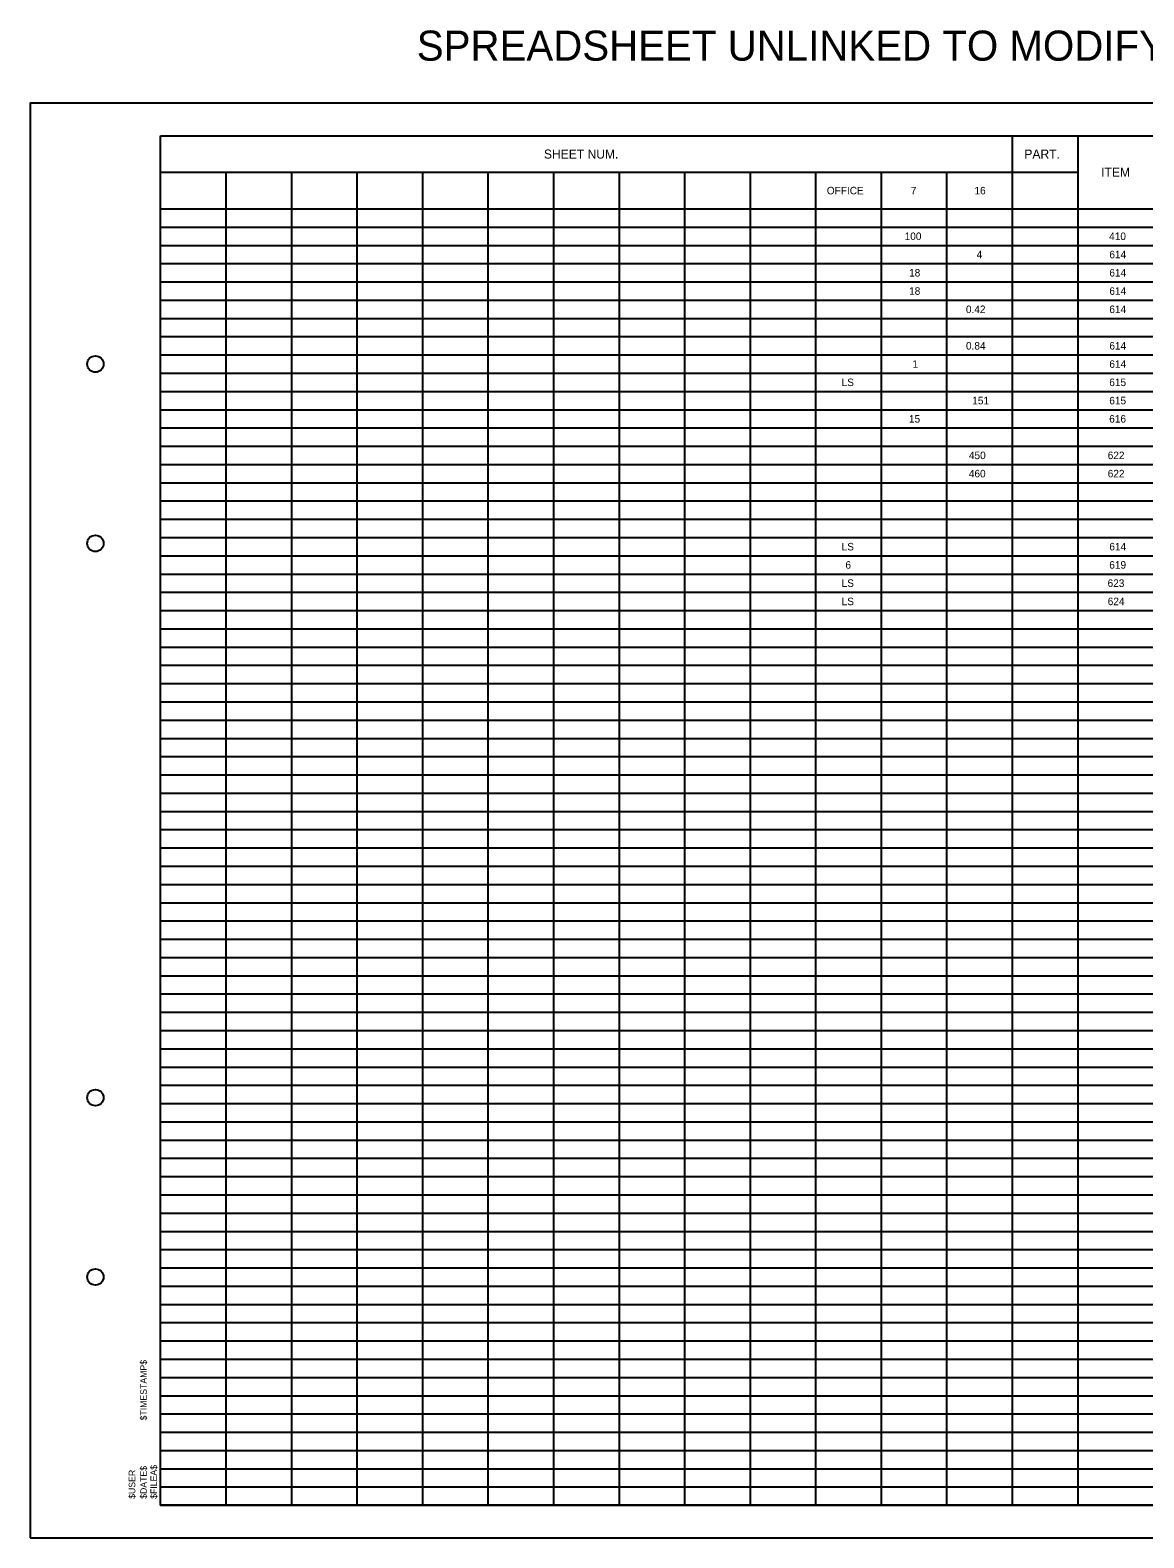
# Model space of a CAD drawing. Extents: x 0 to 34, y 0 to 23.1.
# Drawn here: x 0 to 17.07, y 0 to 23.12 of the extents above; entities that cross this region are included whole.
import ezdxf

# ---------------------------------------------------------------- set-up
doc = ezdxf.new("R2010")
doc.units = 0
for name, color, linetype in [('SH_Border', 7, 'Continuous'), ('SH_Cut_Line', 7, 'Continuous'), ('SH_Data', 7, 'Continuous'), ('SH_Text', 7, 'Continuous')]:
    doc.layers.add(name, color=color, linetype=linetype)

msp = doc.modelspace()

# ---------------------------------------------------------------- linework, layer by layer
at = {"layer": 'SH_Border'}
msp.add_lwpolyline([(2, 21.5), (33.5, 21.5), (33.5, 0.5), (2, 0.5)], close=True, dxfattribs=at)
for centre in [(1, 18), (1, 15.25), (1, 6.75), (1, 4)]:
    msp.add_circle(centre, 0.125, dxfattribs=at)
at = {"layer": 'SH_Cut_Line'}
msp.add_lwpolyline([(0, 0), (34, 0), (34, 22), (0, 22)], close=True, dxfattribs=at)
at = {"layer": 'SH_Text'}
for p, q in [((2, 21.5), (2, 21.5)), ((2, 21.5), (32.5, 21.5)), ((2, 0.5), (2, 21.5)), ((15.06, 0.5), (15.06, 21.5)), ((16.064, 0.5), (16.064, 21.5)), ((2, 20.94), (16.064, 20.94)), ((3.005, 0.5), (3.005, 20.94)), ((4.009, 0.5), (4.009, 20.94)), ((5.014, 0.5), (5.014, 20.94)), ((6.018, 0.5), (6.018, 20.94)), ((7.023, 0.5), (7.023, 20.94)), ((8.028, 0.5), (8.028, 20.94)), ((9.032, 0.5), (9.032, 20.94)), ((10.037, 0.5), (10.037, 20.94)), ((11.041, 0.5), (11.041, 20.94)), ((12.046, 0.5), (12.046, 20.94)), ((13.05, 0.5), (13.05, 20.94)), ((14.055, 0.5), (14.055, 20.94)), ((2, 20.38), (15.06, 20.38)), ((14.055, 20.38), (32.5, 20.38)), ((2, 20.1), (32.5, 20.1)), ((2, 19.82), (32.5, 19.82)), ((2, 19.54), (32.5, 19.54)), ((2, 19.26), (32.5, 19.26)), ((2, 18.98), (32.5, 18.98)), ((2, 18.7), (32.5, 18.7)), ((2, 18.42), (32.5, 18.42)), ((2, 18.14), (32.5, 18.14)), ((2, 17.86), (32.5, 17.86)), ((2, 17.58), (32.5, 17.58)), ((2, 17.3), (32.5, 17.3)), ((2, 17.02), (32.5, 17.02)), ((2, 16.74), (32.5, 16.74)), ((2, 16.46), (32.5, 16.46)), ((2, 16.18), (32.5, 16.18)), ((2, 15.9), (32.5, 15.9)), ((2, 15.62), (32.5, 15.62)), ((2, 15.34), (32.5, 15.34)), ((2, 15.06), (32.5, 15.06)), ((2, 14.78), (32.5, 14.78)), ((2, 14.5), (32.5, 14.5)), ((2, 14.22), (32.5, 14.22)), ((2, 13.94), (32.5, 13.94)), ((2, 13.66), (32.5, 13.66)), ((2, 13.38), (32.5, 13.38)), ((2, 13.1), (32.5, 13.1)), ((2, 12.82), (32.5, 12.82)), ((2, 12.54), (32.5, 12.54)), ((2, 12.26), (32.5, 12.26)), ((2, 11.98), (32.5, 11.98)), ((2, 11.7), (32.5, 11.7)), ((2, 11.42), (32.5, 11.42)), ((2, 11.14), (32.5, 11.14)), ((2, 10.86), (32.5, 10.86)), ((2, 10.58), (32.5, 10.58)), ((2, 10.3), (32.5, 10.3)), ((2, 10.02), (32.5, 10.02)), ((2, 9.74), (32.5, 9.74)), ((2, 9.46), (32.5, 9.46)), ((2, 9.18), (32.5, 9.18)), ((2, 8.9), (32.5, 8.9)), ((2, 8.62), (32.5, 8.62)), ((2, 8.34), (32.5, 8.34)), ((2, 8.06), (32.5, 8.06)), ((2, 7.78), (32.5, 7.78)), ((2, 7.5), (32.5, 7.5)), ((2, 7.22), (32.5, 7.22)), ((2, 6.94), (32.5, 6.94)), ((2, 6.66), (32.5, 6.66)), ((2, 6.38), (32.5, 6.38)), ((2, 6.1), (32.5, 6.1)), ((2, 5.82), (32.5, 5.82)), ((2, 5.54), (32.5, 5.54)), ((2, 5.26), (32.5, 5.26)), ((2, 4.98), (32.5, 4.98)), ((2, 4.7), (32.5, 4.7)), ((2, 4.42), (32.5, 4.42)), ((2, 4.14), (32.5, 4.14)), ((2, 3.86), (32.5, 3.86)), ((2, 3.58), (32.5, 3.58)), ((2, 3.3), (32.5, 3.3)), ((2, 3.02), (32.5, 3.02)), ((2, 2.74), (32.5, 2.74)), ((2, 2.46), (32.5, 2.46)), ((2, 2.18), (32.5, 2.18)), ((2, 1.9), (32.5, 1.9)), ((2, 1.62), (32.5, 1.62)), ((2, 1.34), (32.5, 1.34)), ((2, 1.06), (32.5, 1.06)), ((2, 0.78), (32.5, 0.78)), ((2, 0.5), (32.5, 0.5))]:
    msp.add_line(p, q, dxfattribs=at)

# ---------------------------------------------------------------- texts
at = {"layer": 'SH_Data'}
for s, p in [('$TIMESTAMP$', (1.788, 1.8)), ('$USER', (1.611, 0.598)), ('$DATE$', (1.788, 0.598)), ('$FILEA$', (1.944, 0.598))]:
    msp.add_text(s, height=0.1, rotation=89.9931, dxfattribs=at).set_placement(p)
at = {"layer": 'SH_Text'}
for s, height, p in [('SPREADSHEET UNLINKED TO MODIFY PORTABLE BARRIER ITEMS.', 0.46136, (5.927, 22.652)), ('SHEET NUM.', 0.1384, (7.876, 21.151)), ('PART.', 0.1384, (15.241, 21.151)), ('ITEM', 0.1384, (16.419, 20.871)), ('OFFICE', 0.1153, (12.213, 20.602)), ('7', 0.115, (13.5, 20.602)), ('16', 0.1153, (14.476, 20.602)), ('100', 0.1153, (13.406, 19.902)), ('410', 0.1153, (16.541, 19.902)), ('4', 0.115, (14.509, 19.622)), ('614', 0.1153, (16.544, 19.622)), ('18', 0.1153, (13.474, 19.342)), ('614', 0.1153, (16.544, 19.342)), ('18', 0.1153, (13.474, 19.062)), ('614', 0.1153, (16.544, 19.062)), ('0.42', 0.1153, (14.345, 18.782)), ('614', 0.1153, (16.544, 18.782)), ('0.84', 0.1153, (14.346, 18.222)), ('614', 0.1153, (16.544, 18.222)), ('1', 0.115, (13.525, 17.942)), ('614', 0.1153, (16.544, 17.942)), ('LS', 0.1153, (12.44, 17.662)), ('615', 0.1153, (16.543, 17.662)), ('151', 0.1153, (14.442, 17.382)), ('615', 0.1153, (16.543, 17.382)), ('15', 0.1153, (13.472, 17.102)), ('616', 0.1153, (16.542, 17.102)), ('450', 0.1153, (14.391, 16.542)), ('622', 0.1153, (16.519, 16.542)), ('460', 0.1153, (14.39, 16.262)), ('622', 0.1153, (16.519, 16.262)), ('LS', 0.1153, (12.44, 15.142)), ('614', 0.1153, (16.544, 15.142)), ('6', 0.115, (12.498, 14.862)), ('619', 0.1153, (16.543, 14.862)), ('LS', 0.1153, (12.44, 14.582)), ('623', 0.1153, (16.517, 14.582)), ('LS', 0.1153, (12.44, 14.302)), ('624', 0.1153, (16.519, 14.302))]:
    msp.add_text(s, height=height, dxfattribs=at).set_placement(p)

doc.saveas('drawing.dxf')
